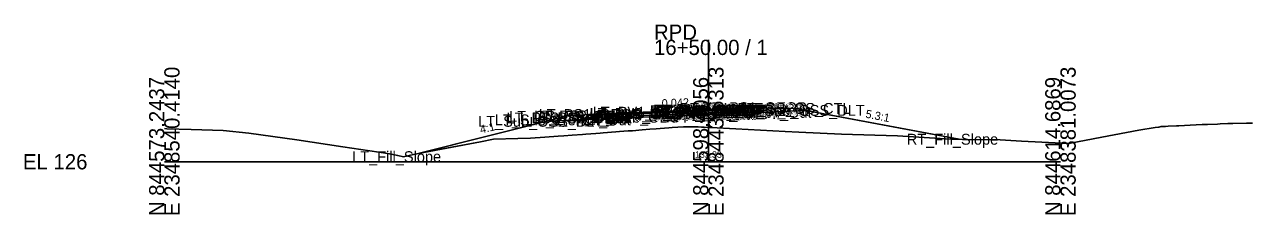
# Model space of a CAD drawing. Extents: x -26 to 2348536, y -510 to 844755.
# Drawn here: x -25.7 to 200, y 1490.3 to 1525.2 of the extents above; entities that cross this region are included whole.
import ezdxf

# ---------------------------------------------------------------- set-up
doc = ezdxf.new("R2010")
doc.units = 0
for name, color, linetype in [('Default', 7, 'Continuous'), ('Exist Cross Section Cell', 7, 'Continuous'), ('Exist XS Center Line Elevation Label', 7, 'Continuous'), ('Exist XS Ground Line', 7, 'Continuous'), ('Prop CMT Pvmt Course 1', 7, 'Continuous'), ('Prop CMT Pvmt Course 2', 7, 'Continuous'), ('Prop CMT Pvmt Course 3', 7, 'Continuous'), ('Prop CMT Pvmt Surface', 7, 'Continuous'), ('Prop CMT Pvmt Surface Shoulder', 7, 'Continuous'), ('Prop CMT Shld Paved Course 1', 7, 'Continuous'), ('Prop CMT Shld Paved Course 2', 7, 'Continuous'), ('Prop CMT Shld Paved Course 3', 7, 'Continuous'), ('Prop CMT Slope Grass', 7, 'Continuous'), ('Prop CMT Subgrade Earthwork', 7, 'Continuous'), ('Prop XS Earthwork Shape', 7, 'Continuous'), ('Prop XS SE Text', 7, 'Continuous'), ('Prop XS Side Slope Text', 7, 'Continuous'), ('Scratch_Level_0', 7, 'Continuous')]:
    doc.layers.add(name, color=color, linetype=linetype)

msp = doc.modelspace()

# ---------------------------------------------------------------- linework, layer by layer
at = {"layer": 'Exist Cross Section Cell'}
for p, q in [((100, 1500), (100, 1522.44)), ((0, 1500), (100, 1500)), ((100, 1500), (164.71, 1500))]:
    msp.add_line(p, q, dxfattribs=at)
at = {"layer": 'Exist XS Ground Line'}
msp.add_lwpolyline([(0, 1506.09), (0.46, 1506.06), (4.92, 1505.91), (10.79, 1505.75), (15.54, 1505.24), (24.36, 1504.05), (32.78, 1502.72), (41.05, 1501.53), (42.91, 1501.14), (43.94, 1500.93), (45.8, 1501.35), (46.72, 1501.55), (58.09, 1503.68), (60.49, 1504.14), (64.98, 1504.28), (67.31, 1504.34), (69.94, 1504.54), (72.37, 1504.68), (73.43, 1504.76), (74.95, 1504.88), (76.84, 1505.03), (77.47, 1505.08), (79.34, 1505.21), (80.08, 1505.26), (80.66, 1505.31), (82.99, 1505.49), (83.64, 1505.54), (85.24, 1505.66), (86.07, 1505.72), (87.83, 1505.86), (89.26, 1505.97), (90.38, 1506.05), (91.13, 1506.12), (92.74, 1506.25), (93.36, 1506.29), (95.41, 1506.42), (96.22, 1506.42), (98.14, 1506.41), (98.75, 1506.38), (99.24, 1506.37), (100, 1506.33), (100.44, 1506.31), (105.03, 1506.07), (114.12, 1505.58), (116.62, 1505.46), (124.45, 1505.05), (130.59, 1504.89), (134.78, 1504.78), (144.55, 1504.18), (145.11, 1504.15), (146.73, 1504.12), (153.65, 1504.01), (157.58, 1503.81), (166.25, 1503.38), (172.33, 1504.53), (179.12, 1505.82), (182.11, 1506.29), (182.77, 1506.39), (183.24, 1506.48), (184.01, 1506.49), (184.48, 1506.52), (186.03, 1506.61), (186.49, 1506.63), (188.58, 1506.73), (190.75, 1506.83), (191.27, 1506.85), (191.77, 1506.88), (193.55, 1506.93), (194.05, 1506.97), (195.47, 1507.01), (196.37, 1507.03), (198.91, 1507.09), (200, 1507.11)], dxfattribs=at)
at = {"layer": 'Prop CMT Pvmt Course 1'}
for p, q in [((100, 1509.61), (88, 1509.11)), ((88, 1508.86), (100, 1509.36)), ((88, 1509.11), (88, 1508.86)), ((100, 1509.61), (104, 1509.78)), ((100, 1509.36), (100, 1509.61)), ((100, 1509.36), (100, 1509.61)), ((104, 1509.53), (100, 1509.36)), ((100, 1509.36), (100, 1509.49)), ((100, 1509.49), (100, 1509.49)), ((100, 1509.49), (100, 1509.36)), ((100, 1509.36), (100, 1509.49)), ((100, 1509.49), (100, 1509.49)), ((100, 1509.49), (100, 1509.36)), ((100, 1509.36), (100, 1509.36)), ((100, 1509.36), (100, 1509.36)), ((104, 1509.78), (104, 1509.53))]:
    msp.add_line(p, q, dxfattribs=at)
at = {"layer": 'Prop CMT Pvmt Course 2'}
for p, q in [((100, 1509.36), (88, 1508.86)), ((88, 1508.52), (100, 1509.03)), ((88, 1508.86), (88, 1508.52)), ((100, 1509.36), (104, 1509.53)), ((100, 1509.03), (100, 1509.36)), ((100, 1509.03), (100, 1509.36)), ((104, 1509.2), (100, 1509.03)), ((104, 1509.53), (104, 1509.2))]:
    msp.add_line(p, q, dxfattribs=at)
at = {"layer": 'Prop CMT Pvmt Course 3'}
for p, q in [((100, 1509.03), (88, 1508.52)), ((88, 1508.19), (100, 1508.7)), ((88, 1508.52), (88, 1508.19)), ((100, 1509.03), (104, 1509.2)), ((100, 1508.7), (100, 1509.03)), ((100, 1508.7), (100, 1509.03)), ((104, 1508.87), (100, 1508.7)), ((104, 1509.2), (104, 1508.87))]:
    msp.add_line(p, q, dxfattribs=at)
at = {"layer": 'Prop CMT Pvmt Surface'}
for q in [(88, 1509.11), (104, 1509.78)]:
    msp.add_line((100, 1509.61), q, dxfattribs=at)
at = {"layer": 'Prop CMT Pvmt Surface Shoulder'}
for p, q in [((104, 1509.78), (108, 1509.95)), ((88, 1509.11), (78, 1508.68))]:
    msp.add_line(p, q, dxfattribs=at)
at = {"layer": 'Prop CMT Shld Paved Course 1'}
for p, q in [((104, 1509.78), (108, 1509.95)), ((108, 1509.95), (108.24, 1509.71)), ((77.74, 1508.42), (88, 1508.86)), ((78, 1508.68), (77.74, 1508.42)), ((88, 1509.11), (78, 1508.68)), ((88, 1508.86), (88, 1509.11)), ((104, 1509.53), (104, 1509.78)), ((108.24, 1509.71), (104, 1509.53))]:
    msp.add_line(p, q, dxfattribs=at)
at = {"layer": 'Prop CMT Shld Paved Course 2'}
for p, q in [((77.39, 1508.07), (88, 1508.52)), ((77.74, 1508.42), (77.39, 1508.07)), ((88, 1508.86), (77.74, 1508.42)), ((88, 1508.52), (88, 1508.86)), ((104, 1509.53), (108.24, 1509.71)), ((104, 1509.2), (104, 1509.53)), ((108.56, 1509.39), (104, 1509.2)), ((108.24, 1509.71), (108.56, 1509.39))]:
    msp.add_line(p, q, dxfattribs=at)
at = {"layer": 'Prop CMT Shld Paved Course 3'}
for p, q in [((76.54, 1507.7), (88, 1508.19)), ((76.89, 1508.05), (76.54, 1507.7)), ((77.39, 1508.07), (76.89, 1508.05)), ((88, 1508.52), (77.39, 1508.07)), ((88, 1508.19), (88, 1508.52)), ((104, 1509.2), (108.56, 1509.39)), ((104, 1508.87), (104, 1509.2)), ((109.38, 1509.09), (104, 1508.87)), ((108.56, 1509.39), (109.06, 1509.41)), ((109.06, 1509.41), (109.38, 1509.09))]:
    msp.add_line(p, q, dxfattribs=at)
at = {"layer": 'Prop CMT Slope Grass'}
for p, q in [((108, 1509.95), (116, 1509.81)), ((74, 1508.36), (46.92, 1501.59)), ((78, 1508.68), (74, 1508.36)), ((116, 1509.81), (146.09, 1504.13))]:
    msp.add_line(p, q, dxfattribs=at)
at = {"layer": 'Prop CMT Subgrade Earthwork'}
for p, q in [((76.54, 1507.7), (70.31, 1507.44)), ((88, 1508.19), (76.54, 1507.7)), ((100, 1508.7), (88, 1508.19)), ((100, 1508.7), (104, 1508.87)), ((104, 1508.87), (109.38, 1509.09)), ((109.38, 1509.09), (117.89, 1509.45))]:
    msp.add_line(p, q, dxfattribs=at)
at = {"layer": 'Prop XS Earthwork Shape'}
msp.add_lwpolyline([(58.09, 1503.68), (60.49, 1504.14), (64.98, 1504.28), (67.31, 1504.34), (69.94, 1504.54), (72.37, 1504.68), (73.43, 1504.76), (74.95, 1504.88), (76.84, 1505.03), (77.47, 1505.08), (79.34, 1505.21), (80.08, 1505.26), (80.66, 1505.31), (82.99, 1505.49), (83.64, 1505.54), (85.24, 1505.66), (86.07, 1505.72), (87.83, 1505.86), (89.26, 1505.97), (90.38, 1506.05), (91.13, 1506.12), (92.74, 1506.25), (93.36, 1506.29), (95.41, 1506.42), (96.22, 1506.42), (98.14, 1506.41), (98.75, 1506.38), (99.24, 1506.37), (100, 1506.33), (100.44, 1506.31), (105.03, 1506.07), (114.12, 1505.58), (116.62, 1505.46), (124.45, 1505.05), (130.59, 1504.89), (134.78, 1504.78), (144.55, 1504.18), (145.11, 1504.15), (146.09, 1504.13), (117.89, 1509.45), (109.38, 1509.09), (104, 1508.87), (100, 1508.7), (88, 1508.19), (76.54, 1507.7), (70.31, 1507.44), (46.92, 1501.59)], close=True, dxfattribs=at)

# ---------------------------------------------------------------- texts
at = {"layer": 'Default'}
msp.add_text('-', height=0.0001, dxfattribs=at).set_placement((0, 1500))
at = {"layer": 'Exist Cross Section Cell'}
for s, p in [('RPD', (90, 1522.44)), ('16+50.00 / 1', (90, 1519.64)), ('EL 126', (-26, 1498.6))]:
    msp.add_text(s, height=2.8, dxfattribs=at).set_placement(p)
for s, p in [('E 2348540.4140', (2.8, 1490)), ('E 2348443.6313', (102.8, 1490)), ('E 2348381.0073', (167.51, 1490)), ('N 844573.2437', (0, 1490)), ('N 844598.4056', (100, 1490)), ('N 844614.6869', (164.71, 1490))]:
    msp.add_text(s, height=2.8, rotation=90, dxfattribs=at).set_placement(p)
at = {"layer": 'Exist XS Center Line Elevation Label'}
msp.add_text('132.33', height=1.2, dxfattribs=at).set_placement((97.55, 1500.73))
at = {"layer": 'Prop XS SE Text'}
msp.add_text('0.042', height=1.5, rotation=2.4238, dxfattribs=at).set_placement((91.45, 1509.99))
at = {"layer": 'Prop XS Side Slope Text'}
for s, rotation, p in [('5.3:1', 349.3149, (128.8, 1508.12)), ('4:1', 14.0362, (58.2, 1505.15))]:
    msp.add_text(s, height=1.5, rotation=rotation, dxfattribs=at).set_placement(p)
at = {"layer": 'Scratch_Level_0'}
for s, p in [('LT_PV2_OEOT', (78.17, 1507.86)), ('LT_PV1_OEOT', (78.74, 1508.11)), ('RT_PV2_OEEOP', (89.26, 1508.36)), ('RT_PV3_OEEOP', (89.26, 1508.03)), ('LT_PV2_OEEOP', (89.31, 1508.36)), ('LT_PV3_OEEOP', (89.31, 1508.03)), ('RT_PV1_OEEOP', (89.83, 1508.49)), ('LT_PV1_OEEOP', (89.87, 1508.49)), ('RT_PV2_IEEOP', (89.91, 1508.36)), ('LT_PV2_IEEOP', (89.95, 1508.36)), ('RT_PV1_IEEOP', (90.47, 1508.49)), ('LT_PV1_IEEOP', (90.52, 1508.49)), ('RT_Sub_Trench_Out', (93.54, 1508.09)), ('PV2_PGL', (93.91, 1508.36)), ('RT_Sub_OEOT', (94.03, 1507.87)), ('RT_PV2_OEOT', (94.13, 1508.53)), ('RT_PV3_OEOT', (94.13, 1508.2)), ('PV1_PGL', (94.47, 1508.61)), ('RT_PV1_OEOT', (94.69, 1508.78)), ('RT_PS3_Shelf_Out', (95, 1508.41)), ('RT_PS2_OEOP', (98.43, 1508.71)), ('RT_PS3_OEOP', (98.75, 1508.39)), ('RT_PS1_OEOP', (98.76, 1508.95)), ('RT_Sub_OSS_DLT', (105.24, 1508.45)), ('RT_GS_OS_CTL', (105.32, 1508.81)), ('LT_Sub_OSS_DLT', (57.67, 1506.44)), ('LT_Sub_Trench_Out', (60.75, 1506.7)), ('LT_PS3_Shelf_Out', (62.88, 1507.05)), ('LT_GS_OS_CTL', (63.37, 1507.36)), ('LT_PS3_OEOP', (67.63, 1507.07)), ('LT_PS2_OEOP', (67.98, 1507.42)), ('LT_PS1_OEOP', (68.8, 1507.68)), ('LT_Sub_OEOT', (78.08, 1507.19)), ('LT_PV3_OEOT', (78.17, 1507.52)), ('RT_Sub_OEEOP', (89.17, 1507.7)), ('LT_Sub_OEEOP', (89.21, 1507.7)), ('RT_Fill_Slope', (136.47, 1503.14)), ('LT_Fill_Slope', (34.52, 1499.94))]:
    msp.add_text(s, height=2, dxfattribs=at).set_placement(p)

doc.saveas('drawing.dxf')
